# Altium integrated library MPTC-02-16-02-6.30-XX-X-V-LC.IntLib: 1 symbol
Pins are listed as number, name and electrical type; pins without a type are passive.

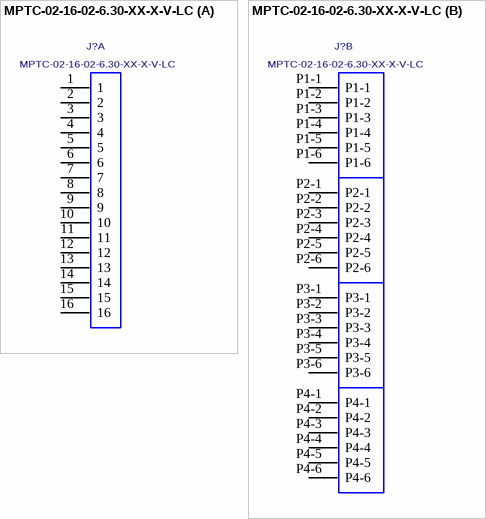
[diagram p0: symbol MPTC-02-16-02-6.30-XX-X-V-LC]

## MPTC-02-16-02-6.30-XX-X-V-LC
designator J?
VERTICAL POWER TERMINAL, 16 SIGNAL PINS, 4 POWER PINS.; MANUFACTURER: SAMTEC
footprint MPTC-02-16-02-6.30-XX-X-V-LC
part A pins: 1, 2, 3, 4, 5, 6, 7, 8, 9, 10, 11, 12, 13, 14, 15, 16
part B pins: P1-1, P1-2, P1-3, P1-4, P1-5, P1-6, P2-1, P2-2, P2-3, P2-4, P2-5, P2-6, P3-1, P3-2, P3-3, P3-4, P3-5, P3-6, P4-1, P4-2, P4-3, P4-4, P4-5, P4-6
